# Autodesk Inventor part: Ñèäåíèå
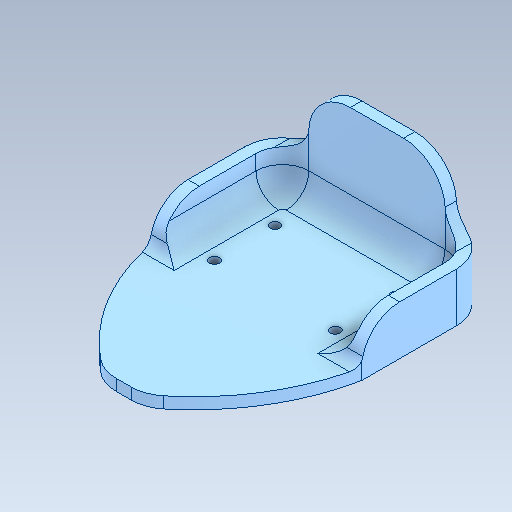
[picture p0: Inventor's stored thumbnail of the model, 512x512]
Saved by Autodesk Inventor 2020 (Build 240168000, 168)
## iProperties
Created: 1900-01
Part Number: Ñèäåíèå
Material: Générique
Document SubType Name: Modeling
Designer: bruno
Density: 1 g/cm^3
Appearance: Par défaut
Author: bruno
Revision Number: ANYUNSPECIFIED
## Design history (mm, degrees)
feature "Base1"
node "Solide1"
